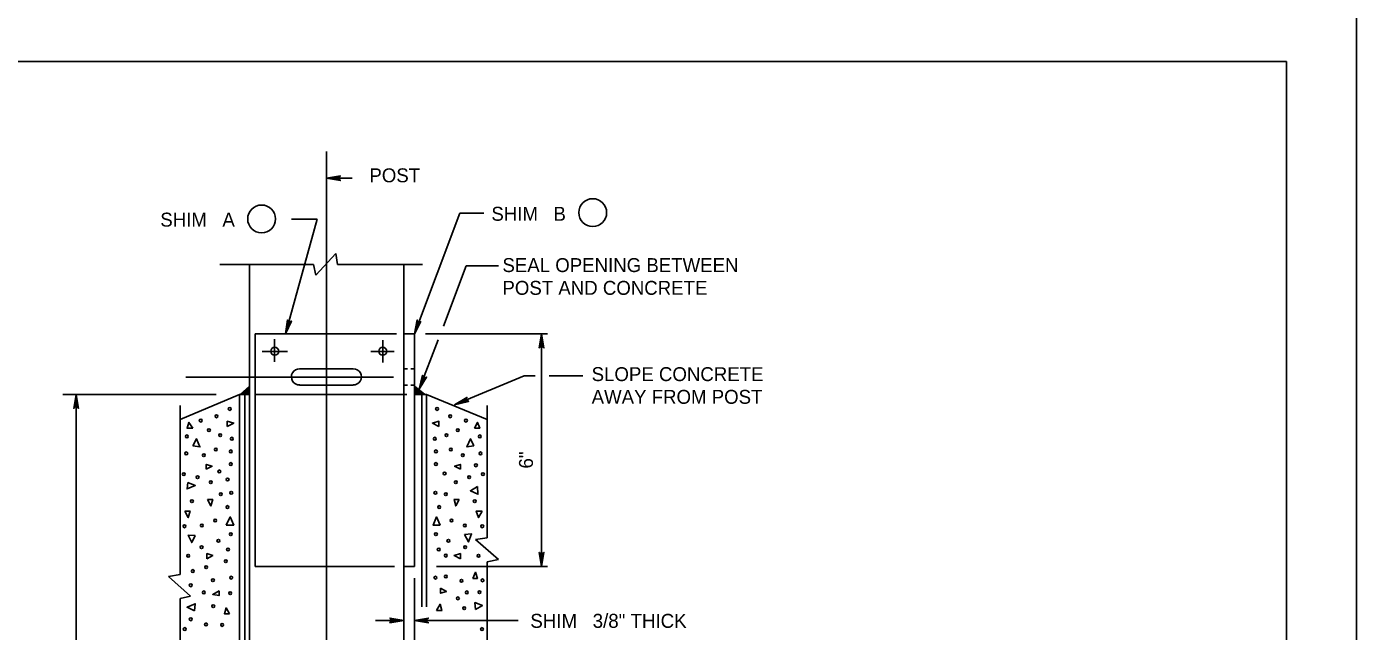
# Model space of a CAD drawing. Extents: x -2340 to 628, y -879 to 309.
# Drawn here: x -1402.6 to -1117.4, y -421.8 to -292.1 of the extents above; entities that cross this region are included whole.
import ezdxf

# ---------------------------------------------------------------- set-up
doc = ezdxf.new("R2010")
doc.units = 0
for name, color, linetype in [('Level 1', 7, 'Continuous'), ('Level 2', 7, 'Continuous'), ('Level 3', 7, 'Continuous'), ('PLT-BNDY', 7, 'Continuous')]:
    doc.layers.add(name, color=color, linetype=linetype)

msp = doc.modelspace()

# ---------------------------------------------------------------- linework, layer by layer
at = {"layer": 'Level 1'}
for p in [(-1918.39, -299.56), (-1132.39, -863.56)]:
    msp.add_line(p, (-1132.39, -299.56), dxfattribs=at)
at = {"layer": 'Level 2'}
for p, q in [((-1340.52, -345.33), (-1336.27, -340.7)), ((-1336.27, -340.7), (-1335.89, -343.08)), ((-1361.14, -343.08), (-1341.02, -343.08)), ((-1354.77, -519.58), (-1354.77, -343.08)), ((-1341.02, -343.08), (-1340.52, -345.33)), ((-1335.89, -343.08), (-1317.64, -343.08)), ((-1321.64, -519.58), (-1321.64, -343.08)), ((-1323.27, -357.95), (-1353.53, -357.95)), ((-1353.53, -407.83), (-1353.53, -357.95)), ((-1349.39, -363.95), (-1349.39, -359.08)), ((-1319.39, -357.95), (-1321.64, -357.95)), ((-1319.39, -407.83), (-1319.39, -357.95)), ((-1346.64, -361.7), (-1352.02, -361.7)), ((-1323.77, -361.7), (-1328.77, -361.7)), ((-1326.14, -364.08), (-1326.14, -359.33)), ((-1323.85, -367.2), (-1368.39, -367.2)), ((-1332.52, -365.45), (-1344.02, -365.45)), ((-1321.64, -365.45), (-1320.88, -365.45)), ((-1320.17, -365.45), (-1319.39, -365.45)), ((-1354.77, -369.2), (-1356.77, -370.95)), ((-1354.77, -369.45), (-1356.52, -370.95)), ((-1354.77, -369.83), (-1356.27, -370.95)), ((-1354.77, -370.08), (-1355.89, -370.83)), ((-1355.77, -538.08), (-1355.77, -370.48)), ((-1354.77, -370.33), (-1355.64, -370.95)), ((-1354.77, -370.58), (-1355.27, -370.83)), ((-1332.52, -368.95), (-1344.02, -368.95)), ((-1321.64, -368.95), (-1320.88, -368.95)), ((-1320.17, -368.95), (-1319.39, -368.95)), ((-1319.39, -369.2), (-1317.14, -370.95)), ((-1319.39, -369.45), (-1317.52, -370.95)), ((-1319.39, -369.83), (-1317.89, -370.95)), ((-1319.39, -370.08), (-1318.27, -370.95)), ((-1319.39, -370.33), (-1318.52, -370.95)), ((-1319.39, -370.58), (-1318.89, -370.95)), ((-1356.89, -370.95), (-1369.64, -376.33)), ((-1369.64, -409.58), (-1369.64, -373.33)), ((-1354.77, -370.95), (-1356.89, -370.95)), ((-1356.89, -538.08), (-1356.89, -370.95)), ((-1354.77, -370.83), (-1355.02, -370.95)), ((-1321.02, -370.95), (-1353.53, -370.95)), ((-1319.39, -370.83), (-1319.27, -370.95)), ((-1316.77, -370.95), (-1319.39, -370.95)), ((-1317.77, -416.48), (-1317.77, -370.95)), ((-1316.77, -370.95), (-1303.77, -376.33)), ((-1316.77, -416.48), (-1316.77, -370.95)), ((-1303.77, -401.7), (-1303.77, -373.33)), ((-1306.27, -402.08), (-1303.77, -401.7)), ((-1301.39, -406.33), (-1306.27, -402.08)), ((-1303.77, -406.83), (-1301.39, -406.33)), ((-1303.77, -451.2), (-1303.77, -406.83)), ((-1372.14, -409.95), (-1369.64, -409.58)), ((-1367.39, -414.2), (-1372.14, -409.95)), ((-1323.64, -407.83), (-1353.53, -407.83)), ((-1319.39, -407.83), (-1321.64, -407.83)), ((-1369.64, -414.7), (-1367.39, -414.2)), ((-1369.64, -460.08), (-1369.64, -414.7))]:
    msp.add_line(p, q, dxfattribs=at)
for points in [[(-1366.89, -378.2), (-1368.14, -378.2), (-1367.77, -376.95)], [(-1359.52, -377.83), (-1359.52, -376.7), (-1358.14, -377.08)], [(-1314.14, -377.83), (-1314.14, -376.7), (-1315.52, -377.08)], [(-1306.52, -378.2), (-1305.39, -378.2), (-1305.89, -376.95)], [(-1366.89, -381.95), (-1365.39, -382.2), (-1366.14, -380.45)], [(-1306.64, -381.95), (-1308.14, -382.2), (-1307.39, -380.45)], [(-1364.02, -386.95), (-1364.02, -385.95), (-1362.77, -386.33)], [(-1309.52, -386.95), (-1309.52, -385.95), (-1310.77, -386.33)], [(-1368.02, -389.83), (-1368.14, -391.2), (-1366.39, -390.45)], [(-1363.77, -393.45), (-1362.64, -393.45), (-1363.02, -394.83)], [(-1309.77, -393.45), (-1310.89, -393.45), (-1310.52, -394.83)], [(-1305.89, -390.7), (-1305.77, -392.33), (-1307.39, -391.58)], [(-1368.64, -395.95), (-1367.52, -395.95), (-1367.89, -397.33)], [(-1304.89, -395.95), (-1306.14, -395.95), (-1305.64, -397.33)], [(-1359.77, -398.95), (-1358.14, -398.95), (-1358.89, -397.2)], [(-1313.89, -398.95), (-1315.39, -398.95), (-1314.64, -397.2)], [(-1366.39, -401.2), (-1367.89, -401.08), (-1367.14, -402.7)], [(-1308.64, -400.95), (-1307.14, -400.83), (-1307.77, -402.58)], [(-1363.89, -406.2), (-1363.89, -405.08), (-1362.64, -405.45)], [(-1309.52, -406.2), (-1309.52, -405.08), (-1310.89, -405.45)], [(-1306.89, -410.43), (-1305.89, -410.43), (-1306.27, -409.05)], [(-1361.27, -413.08), (-1361.27, -414.08), (-1362.64, -413.83)], [(-1313.77, -412.45), (-1313.77, -413.58), (-1312.52, -413.2)], [(-1366.52, -417.33), (-1366.39, -415.83), (-1368.14, -416.58)], [(-1314.63, -417.29), (-1313.5, -417.29), (-1313.88, -415.92)], [(-1306.31, -417.08), (-1306.43, -415.58), (-1304.81, -416.21)], [(-1359.02, -417.95), (-1360.14, -417.95), (-1359.77, -416.7)]]:
    msp.add_lwpolyline(points, close=True, dxfattribs=at)
for centre, radius in [((-1349.36, -361.69), 0.856), ((-1326.19, -361.69), 0.856), ((-1365.22, -376.56), 0.301), ((-1361.85, -375.62), 0.301), ((-1359.01, -374.05), 0.301), ((-1314.54, -374.05), 0.301), ((-1311.71, -375.62), 0.301), ((-1308.34, -376.56), 0.301), ((-1363.46, -378.58), 0.301), ((-1310.09, -378.58), 0.301), ((-1368.18, -379.93), 0.301), ((-1361.04, -379.66), 0.301), ((-1358.54, -380.43), 0.301), ((-1315.02, -380.43), 0.301), ((-1312.52, -379.66), 0.301), ((-1305.38, -379.93), 0.301), ((-1368.31, -383.57), 0.301), ((-1364.54, -383.97), 0.301), ((-1361.98, -382.76), 0.301), ((-1358.78, -383.15), 0.301), ((-1314.78, -383.15), 0.301), ((-1311.58, -382.76), 0.301), ((-1309.02, -383.97), 0.301), ((-1305.24, -383.57), 0.301), ((-1368.85, -388.02), 0.301), ((-1361.23, -387.43), 0.301), ((-1358.78, -385.87), 0.301), ((-1314.78, -385.87), 0.301), ((-1312.92, -387.88), 0.301), ((-1306.19, -386.13), 0.301), ((-1304.7, -388.02), 0.301), ((-1365.89, -388.69), 0.301), ((-1363.06, -389.77), 0.301), ((-1359.45, -389.18), 0.301), ((-1310.5, -389.77), 0.301), ((-1307.67, -388.69), 0.301), ((-1367.1, -393.82), 0.301), ((-1360.91, -392.33), 0.301), ((-1358.66, -392.02), 0.301), ((-1314.9, -392.02), 0.301), ((-1312.65, -392.33), 0.301), ((-1306.46, -393.82), 0.301), ((-1359.49, -395.09), 0.301), ((-1314.07, -395.09), 0.301), ((-1368.72, -399.21), 0.301), ((-1364.98, -399.04), 0.301), ((-1362.12, -397.99), 0.301), ((-1311.44, -397.99), 0.301), ((-1308.57, -399.04), 0.301), ((-1304.84, -399.21), 0.301), ((-1361.44, -402.31), 0.301), ((-1358.78, -400.89), 0.301), ((-1314.78, -400.89), 0.301), ((-1312.11, -402.31), 0.301), ((-1365.03, -403.7), 0.301), ((-1359.37, -404.2), 0.301), ((-1314.19, -404.2), 0.301), ((-1308.53, -403.7), 0.301), ((-1367.91, -405.54), 0.301), ((-1364.07, -407.97), 0.301), ((-1359.84, -406.68), 0.301), ((-1312.66, -405.5), 0.301), ((-1305.65, -405.54), 0.301), ((-1366.93, -408.81), 0.301), ((-1362.6, -410.78), 0.301), ((-1358.66, -410.23), 0.301), ((-1314.9, -410.23), 0.301), ((-1312.65, -409.99), 0.301), ((-1309.3, -410.9), 0.301), ((-1304.77, -410.8), 0.301), ((-1367.37, -411.87), 0.301), ((-1364.56, -413.38), 0.301), ((-1358.9, -413.54), 0.301), ((-1308.17, -413.38), 0.301), ((-1305.44, -413.35), 0.301), ((-1362.52, -416.33), 0.301), ((-1310.05, -414.66), 0.301), ((-1367.37, -419.16), 0.301), ((-1308.72, -416.77), 0.301), ((-1368.65, -421.25), 0.301), ((-1364.09, -420.24), 0.301), ((-1360.63, -420.37), 0.301), ((-1304.9, -421.25), 0.301)]:
    msp.add_circle(centre, radius, dxfattribs=at)
for centre, start, end in [((-1344.04, -367.17), 89.2551, 271.9772), ((-1332.5, -367.17), 268.0228, 90.7449)]:
    msp.add_arc(centre, 1.74, start, end, dxfattribs=at)
at = {"layer": 'Level 3'}
for p, q in [((-1338.27, -463.95), (-1338.27, -318.87)), ((-1332.77, -324.58), (-1338.27, -324.58)), ((-1340.27, -333.33), (-1347.02, -357.95)), ((-1340.27, -333.33), (-1345.77, -333.33)), ((-1309.64, -332.08), (-1319.39, -357.95)), ((-1304.52, -332.08), (-1309.64, -332.08)), ((-1308.27, -343.33), (-1313.14, -356.33)), ((-1301.39, -343.33), (-1308.27, -343.33)), ((-1314.27, -359.2), (-1318.39, -369.83)), ((-1290.89, -357.95), (-1317.02, -357.95)), ((-1292.14, -407.83), (-1292.14, -357.95)), ((-1295.89, -366.95), (-1310.77, -373.2)), ((-1293.52, -366.95), (-1295.89, -366.95)), ((-1283.27, -366.95), (-1290.52, -366.95)), ((-1361.89, -370.95), (-1394.81, -370.95)), ((-1391.95, -370.95), (-1391.95, -520.83)), ((-1319.39, -410.33), (-1319.39, -432.82)), ((-1290.89, -407.83), (-1314.64, -407.83)), ((-1327.77, -419.41), (-1321.64, -419.41)), ((-1319.39, -419.41), (-1297.18, -419.41))]:
    msp.add_line(p, q, dxfattribs=at)
for points in [[(-1335.39, -324.95), (-1335.52, -324.7), (-1338.27, -324.58), (-1335.39, -324.95), (-1335.27, -325.08), (-1338.27, -324.58), (-1335.52, -324.45), (-1335.39, -324.2), (-1338.27, -324.58), (-1335.27, -324.08), (-1335.39, -324.2)], [(-1345.89, -355.33), (-1346.14, -355.33), (-1347.02, -357.95), (-1345.89, -355.33), (-1345.77, -355.2), (-1347.02, -357.95), (-1346.39, -355.33), (-1346.64, -355.08), (-1347.02, -357.95), (-1346.64, -354.95), (-1346.64, -355.08)], [(-1318.14, -355.45), (-1318.39, -355.45), (-1319.39, -357.95), (-1318.14, -355.45), (-1318.02, -355.33), (-1319.39, -357.95), (-1318.52, -355.33), (-1318.77, -355.2), (-1319.39, -357.95), (-1318.77, -354.95), (-1318.77, -355.2)], [(-1292.52, -360.83), (-1292.39, -360.7), (-1292.14, -357.95), (-1292.52, -360.83), (-1292.64, -360.95), (-1292.14, -357.95), (-1292.02, -360.7), (-1291.77, -360.83), (-1292.14, -357.95), (-1291.64, -360.95), (-1291.77, -360.83)], [(-1316.89, -367.33), (-1317.14, -367.33), (-1318.39, -369.83), (-1316.89, -367.33), (-1316.77, -367.2), (-1318.39, -369.83), (-1317.52, -367.2), (-1317.64, -367.08), (-1318.39, -369.83), (-1317.64, -366.83), (-1317.64, -367.08)], [(-1392.33, -373.83), (-1392.2, -373.7), (-1391.95, -370.95), (-1392.33, -373.83), (-1392.45, -373.95), (-1391.95, -370.95), (-1391.83, -373.7), (-1391.58, -373.7), (-1391.95, -370.95), (-1391.45, -373.95), (-1391.58, -373.7)], [(-1307.89, -372.33), (-1308.14, -372.2), (-1310.77, -373.2), (-1307.89, -372.33), (-1307.77, -372.45), (-1310.77, -373.2), (-1308.27, -371.95), (-1308.27, -371.83), (-1310.77, -373.2), (-1308.14, -371.58), (-1308.27, -371.83)], [(-1291.77, -404.95), (-1292.02, -404.95), (-1292.14, -407.83), (-1291.77, -404.95), (-1291.64, -404.83), (-1292.14, -407.83), (-1292.27, -404.95), (-1292.52, -404.95), (-1292.14, -407.83), (-1292.64, -404.83), (-1292.52, -404.95)], [(-1324.52, -419.04), (-1324.52, -419.16), (-1321.64, -419.41), (-1324.52, -419.04), (-1324.64, -418.91), (-1321.64, -419.41), (-1324.52, -419.54), (-1324.52, -419.66), (-1321.64, -419.41), (-1324.64, -419.91), (-1324.52, -419.66)], [(-1316.64, -419.79), (-1316.77, -419.54), (-1319.39, -419.41), (-1316.64, -419.79), (-1316.39, -419.91), (-1319.39, -419.41), (-1316.77, -419.16), (-1316.64, -419.04), (-1319.39, -419.41), (-1316.39, -418.91), (-1316.64, -419.04)]]:
    msp.add_lwpolyline(points, dxfattribs=at)
for centre in [(-1352.17, -333.3), (-1281.15, -331.95)]:
    msp.add_circle(centre, 2.98, dxfattribs=at)
at = {"layer": 'PLT-BNDY'}
msp.add_lwpolyline([(-1958.39, -284.56), (-1117.39, -284.56), (-1117.39, -878.56), (-1958.39, -878.56)], close=True, dxfattribs=at)

# ---------------------------------------------------------------- texts
at = {"layer": 'Level 2'}
for s, p in [('  POST', (-1331.27, -325.45)), ('SHIM   B ', (-1302.89, -333.7)), ('SHIM   A ', (-1373.89, -334.95)), ('SEAL OPENING BETWEEN', (-1300.52, -344.7)), ('POST AND CONCRETE', (-1300.52, -349.58)), ('SLOPE CONCRETE', (-1281.39, -368.08)), ('AWAY FROM POST', (-1281.39, -372.95))]:
    msp.add_text(s, height=2.988, dxfattribs=at).set_placement(p)
at = {"layer": 'Level 3'}
for s, rotation, p in [('6"', 90, (-1293.97, -386.83)), ('SHIM   3/8" THICK', 360, (-1294.54, -420.99))]:
    msp.add_text(s, height=3, rotation=rotation, dxfattribs=at).set_placement(p)

doc.saveas('drawing.dxf')
